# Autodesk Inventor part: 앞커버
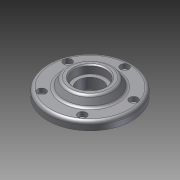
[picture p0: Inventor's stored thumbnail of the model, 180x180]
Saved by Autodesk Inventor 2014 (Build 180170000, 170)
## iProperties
Company: 한국ATC센터
Created: 2014-03
Part Number: 앞커버
Document SubType Name: Modeling
Designer: KYOUNG IL JANG
Density: 1 g/cm^3
Material: 일반
Appearance: Default
Author: KYOUNG IL JANG
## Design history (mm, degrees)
sketch "스케치1"
  geometry: C1 r 26 at (0, 0); C2 r 40 at (0, 0); 1 further point
  constraints: 2 centre point, 2 coincident
  dimensions: "d0" = 52 diameter of C1; "d1" = 80 diameter of C2
extrude "돌출1" new body sketch "스케치1" distance "d2" = 8; taper "d3" = 0 deg
extrude "돌출2" join sketch "스케치1" distance "d4" = 5; taper "d5" = 0 deg
sketch "스케치2"
  geometry: C1 r 25 at (0, 0); 1 further point
  constraints: 1 centre point, 1 coincident
  dimensions: "d6" = 50 diameter of C1
extrude "돌출3" join sketch "스케치2" distance "d7" = 8; taper "d8" = -30 deg
sketch "스케치3"
  geometry: C1 r 1.729 at (0, 33) reference; 1 further point
hole "구멍1" sketch "스케치3" at (0, 33) diameter "d9" = 4.5; stored, may be unused: countersink angle "d13" = 90 deg, drill point angle "d15" = 118 deg; dims "d10" = 6, "d11" = 8, "d12" = 4.4, "d14" = 8
hole "구멍2" diameter "d21" = 23; stored, may be unused: countersink angle "d25" = 90 deg, drill point angle "d27" = 118 deg; dims "d19" = 10, "d20" = 10, "d22" = 6, "d23" = 30, "d24" = 8, "d26" = 8
fillet "모깎기1" dims "d28" = 3, "d29" = 0.3
hole "구멍3" diameter "d32" = 40; stored, may be unused: countersink angle "d36" = 90 deg, drill point angle "d38" = 0 deg; dims "d30" = 10, "d31" = 10, "d33" = 6, "d34" = 30, "d35" = 8, "d37" = 3
fillet "모깎기2" dims "d39" = 3
chamfer "모따기1" distance "d40" = 1; stored, may be unused: second distance "d41" = 2, angle "d42" = 45 deg
node "솔리드1"
pattern_circular "원형 패턴1" dims angle "d17" = 360 deg
node "참조1"
